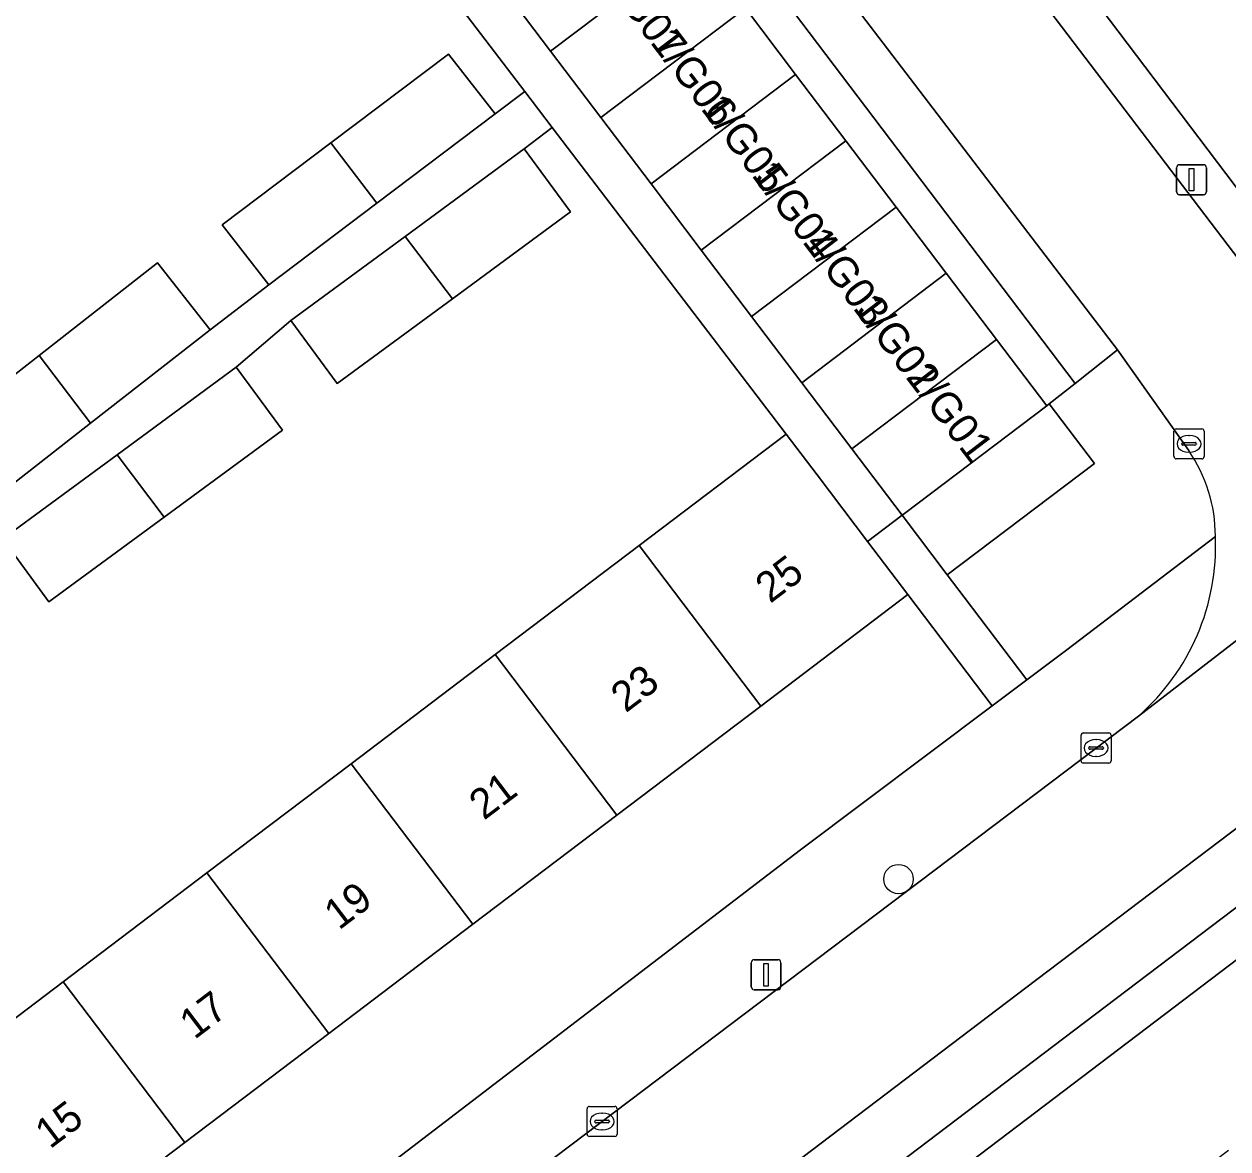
# Model space of a CAD drawing. Extents: x 160030 to 160839, y 385325 to 386450.
# Drawn here: x 160257.86 to 160297.9, y 385897.84 to 385935.27 of the extents above; entities that cross this region are included whole.
import ezdxf

# ---------------------------------------------------------------- set-up
doc = ezdxf.new("R2010")
doc.units = 0
for name, color, linetype in [('IMGEO_Boom', 7, 'Continuous'), ('IMGEO_Erf', 7, 'Continuous'), ('IMGEO_Groenvoorziening', 7, 'Continuous'), ('IMGEO_Kolk', 7, 'Continuous'), ('IMGEO_Lage_trafo', 7, 'Continuous'), ('IMGEO_Lichtmast', 7, 'Continuous'), ('IMGEO_Pand', 7, 'Continuous'), ('IMGEO_Pand_nummerreeks', 7, 'Continuous'), ('IMGEO_Parkeervlak_open', 7, 'Continuous'), ('IMGEO_Rijbaan_lokaal_open', 7, 'Continuous'), ('IMGEO_Voetpad_open', 7, 'Continuous')]:
    doc.layers.add(name, color=color, linetype=linetype)

msp = doc.modelspace()

# ---------------------------------------------------------------- linework, layer by layer
at = {"layer": 'IMGEO_Boom'}
msp.add_circle((160286.944, 385906.816), 0.489, dxfattribs=at)
at = {"layer": 'IMGEO_Erf'}
msp.add_lwpolyline([(160271.131, 385951.947), (160270.16, 385951.238), (160271.83, 385949.032), (160273.5, 385946.826), (160275.171, 385944.62), (160276.841, 385942.414), (160278.511, 385940.208), (160280.181, 385938.002), (160281.852, 385935.796), (160283.522, 385933.59), (160285.192, 385931.384), (160286.862, 385929.178), (160288.533, 385926.972), (160290.203, 385924.766), (160291.873, 385922.56), (160291.96, 385922.629), (160292.815, 385923.307)], close=True, dxfattribs=at)
for points in [[(160254.778, 385921.445), (160258.359, 385924.242), (160262.305, 385927.325), (160264.052, 385925.088), (160266.008, 385926.593), (160264.451, 385928.585), (160268.069, 385931.317), (160271.974, 385934.265), (160273.53, 385932.273), (160274.513, 385933.022), (160267.063, 385942.785)], [(160254.367, 385899.764), (160259.157, 385903.393), (160263.946, 385907.024), (160268.736, 385910.654), (160273.526, 385914.284), (160278.316, 385917.915), (160283.21, 385921.624), (160275.43, 385931.82), (160274.5, 385931.111), (160276.039, 385929.017), (160272.107, 385926.125), (160268.271, 385923.304), (160266.731, 385925.397), (160264.92, 385923.85), (160266.459, 385921.756), (160262.526, 385918.863), (160258.691, 385916.043), (160257.151, 385918.136)], [(160326.435, 385925.58), (160256.578, 385872.537), (160259.529, 385868.732), (160264.444, 385872.453), (160269.226, 385876.074), (160274.008, 385879.694), (160278.789, 385883.315), (160283.571, 385886.936), (160288.353, 385890.556), (160293.136, 385894.177), (160297.918, 385897.798)], [(160243.764, 385877.424), (160267.87, 385895.673), (160283.686, 385907.791), (160290.062, 385912.583), (160287.26, 385916.28), (160282.366, 385912.571), (160277.576, 385908.94), (160272.787, 385905.31), (160267.997, 385901.68), (160263.207, 385898.05), (160258.418, 385894.42), (160253.628, 385890.789)]]:
    msp.add_lwpolyline(points, dxfattribs=at)
at = {"layer": 'IMGEO_Groenvoorziening'}
msp.add_lwpolyline([(160296.595, 385921.073), (160294.227, 385924.426), (160292.815, 385923.307), (160291.96, 385922.629), (160293.467, 385920.64), (160288.567, 385916.938), (160289.125, 385916.201), (160291.211, 385913.446), (160292.54, 385914.445), (160297.485, 385918.22)], dxfattribs=at)
msp.add_arc((160292.466, 385918.22), 5.019, 0.0052, 34.6456, dxfattribs=at)
at = {"layer": 'IMGEO_Kolk'}
for p, q in [((160296.107, 385920.871), (160296.107, 385921.723)), ((160296.182, 385921.797), (160297.034, 385921.797)), ((160297.108, 385921.723), (160297.108, 385920.871)), ((160296.366, 385921.291), (160296.366, 385921.303)), ((160296.804, 385921.254), (160296.406, 385921.254)), ((160296.409, 385921.34), (160296.807, 385921.34)), ((160296.595, 385921.577), (160296.62, 385921.577)), ((160296.85, 385921.303), (160296.85, 385921.291)), ((160296.618, 385921.017), (160296.593, 385921.017)), ((160297.034, 385920.797), (160296.182, 385920.797)), ((160293.015, 385910.751), (160293.015, 385911.603)), ((160293.09, 385911.677), (160293.942, 385911.677)), ((160294.016, 385911.603), (160294.016, 385910.751)), ((160293.317, 385911.22), (160293.715, 385911.22)), ((160293.503, 385911.457), (160293.528, 385911.457)), ((160293.274, 385911.171), (160293.274, 385911.183)), ((160293.712, 385911.134), (160293.314, 385911.134)), ((160293.526, 385910.897), (160293.501, 385910.897)), ((160293.758, 385911.183), (160293.758, 385911.171)), ((160293.942, 385910.677), (160293.09, 385910.677)), ((160276.662, 385899.25), (160277.514, 385899.25)), ((160276.587, 385898.324), (160276.587, 385899.176)), ((160276.889, 385898.793), (160277.287, 385898.793)), ((160277.075, 385899.03), (160277.1, 385899.03)), ((160277.588, 385899.176), (160277.588, 385898.324)), ((160276.846, 385898.744), (160276.846, 385898.756)), ((160277.284, 385898.707), (160276.886, 385898.707)), ((160277.098, 385898.47), (160277.073, 385898.47)), ((160277.33, 385898.756), (160277.33, 385898.744)), ((160277.514, 385898.25), (160276.662, 385898.25))]:
    msp.add_line(p, q, dxfattribs=at)
for points in [[(160296.107, 385920.871), (160296.107, 385921.723)], [(160296.182, 385921.797), (160297.034, 385921.797)], [(160297.108, 385921.723), (160297.108, 385920.871)], [(160297.034, 385920.797), (160296.182, 385920.797)], [(160293.015, 385910.751), (160293.015, 385911.603)], [(160293.09, 385911.677), (160293.942, 385911.677)], [(160294.016, 385911.603), (160294.016, 385910.751)], [(160293.942, 385910.677), (160293.09, 385910.677)], [(160276.662, 385899.25), (160277.514, 385899.25)], [(160276.587, 385898.324), (160276.587, 385899.176)], [(160277.588, 385899.176), (160277.588, 385898.324)], [(160277.514, 385898.25), (160276.662, 385898.25)]]:
    msp.add_lwpolyline(points, dxfattribs=at)
for centre, radius, start, end in [((160296.184, 385921.721), 0.0765, 91.552, 178.448), ((160296.184, 385921.721), 0.0765, 91.552, 178.448), ((160297.032, 385921.721), 0.0765, 1.552, 88.448), ((160297.032, 385921.721), 0.0765, 1.552, 88.448), ((160296.406, 385921.3), 0.0403, 85.8775, 175.7526), ((160296.403, 385921.29), 0.0366, 178.938, 274.7102), ((160296.807, 385921.297), 0.043, 264.8664, 352.4533), ((160296.811, 385921.302), 0.0386, 1.7309, 96.639), ((160296.184, 385920.873), 0.0765, 181.552, 268.448), ((160296.184, 385920.873), 0.0765, 181.552, 268.448), ((160297.032, 385920.873), 0.0765, 271.552, 358.448), ((160297.032, 385920.873), 0.0765, 271.552, 358.448), ((160293.092, 385911.601), 0.0765, 91.552, 178.448), ((160293.092, 385911.601), 0.0765, 91.552, 178.448), ((160293.94, 385911.601), 0.0765, 1.552, 88.448), ((160293.94, 385911.601), 0.0765, 1.552, 88.448), ((160293.314, 385911.18), 0.0403, 85.8775, 175.7526), ((160293.719, 385911.182), 0.0386, 1.7309, 96.639), ((160293.311, 385911.17), 0.0366, 178.938, 274.7102), ((160293.715, 385911.177), 0.043, 264.8664, 352.4533), ((160293.092, 385910.753), 0.0765, 181.552, 268.448), ((160293.092, 385910.753), 0.0765, 181.552, 268.448), ((160293.94, 385910.753), 0.0765, 271.552, 358.448), ((160293.94, 385910.753), 0.0765, 271.552, 358.448), ((160276.664, 385899.174), 0.0765, 91.552, 178.448), ((160276.664, 385899.174), 0.0765, 91.552, 178.448), ((160277.512, 385899.174), 0.0765, 1.552, 88.448), ((160277.512, 385899.174), 0.0765, 1.552, 88.448), ((160276.886, 385898.753), 0.0403, 85.8775, 175.7526), ((160277.291, 385898.755), 0.0386, 1.7309, 96.639), ((160276.883, 385898.743), 0.0366, 178.938, 274.7102), ((160277.287, 385898.75), 0.043, 264.8664, 352.4533), ((160276.664, 385898.326), 0.0765, 181.552, 268.448), ((160276.664, 385898.326), 0.0765, 181.552, 268.448), ((160277.512, 385898.326), 0.0765, 271.552, 358.448), ((160277.512, 385898.326), 0.0765, 271.552, 358.448)]:
    msp.add_arc(centre, radius, start, end, dxfattribs=at)
for centre, major_axis, ratio, start_param, end_param in [((160296.594, 385921.297), (-0.387, 0.002), 0.722429, 4.712389, 7.853982), ((160296.619, 385921.297), (-0.39, 0.002), 0.717154, 1.570796, 4.712389), ((160293.502, 385911.177), (-0.387, 0.002), 0.722429, 4.712389, 7.853982), ((160293.527, 385911.177), (-0.39, 0.002), 0.717154, 1.570796, 4.712389), ((160277.074, 385898.75), (-0.387, 0.002), 0.722429, 4.712389, 7.853982), ((160277.099, 385898.75), (-0.39, 0.002), 0.717154, 1.570796, 4.712389)]:
    msp.add_ellipse(centre, major_axis=major_axis, ratio=ratio, start_param=start_param, end_param=end_param, dxfattribs=at)
at = {"layer": 'IMGEO_Lage_trafo'}
msp.add_lwpolyline([(160293.467, 385920.64), (160291.96, 385922.629), (160291.873, 385922.56), (160287.149, 385918.984), (160287.066, 385918.921), (160288.567, 385916.938)], close=True, dxfattribs=at)
at = {"layer": 'IMGEO_Lichtmast'}
for p, q in [((160296.194, 385929.686), (160296.194, 385930.486)), ((160296.194, 385930.486), (160296.194, 385929.686)), ((160296.294, 385930.586), (160297.084, 385930.586)), ((160297.084, 385930.586), (160296.294, 385930.586)), ((160297.184, 385930.486), (160297.184, 385929.686)), ((160297.184, 385929.686), (160297.184, 385930.486)), ((160297.084, 385929.586), (160296.294, 385929.586)), ((160296.294, 385929.586), (160297.084, 385929.586)), ((160282.043, 385903.232), (160282.043, 385904.032)), ((160282.043, 385904.032), (160282.043, 385903.232)), ((160282.143, 385904.132), (160282.933, 385904.132)), ((160282.933, 385904.132), (160282.143, 385904.132)), ((160283.033, 385904.032), (160283.033, 385903.232)), ((160283.033, 385903.232), (160283.033, 385904.032)), ((160282.933, 385903.132), (160282.143, 385903.132)), ((160282.143, 385903.132), (160282.933, 385903.132))]:
    msp.add_line(p, q, dxfattribs=at)
for points in [[(160296.614, 385930.461), (160296.764, 385930.461), (160296.764, 385929.711), (160296.614, 385929.711), (160296.614, 385930.461)], [(160282.463, 385904.007), (160282.613, 385904.007), (160282.613, 385903.257), (160282.463, 385903.257), (160282.463, 385904.007)]]:
    msp.add_lwpolyline(points, dxfattribs=at)
for centre, start, end in [((160296.294, 385930.486), 90, 180), ((160296.294, 385930.486), 90, 180), ((160297.084, 385930.486), 0, 90), ((160297.084, 385930.486), 360, 90), ((160296.294, 385929.686), 180, 270), ((160296.294, 385929.686), 180, 270), ((160297.084, 385929.686), 270, 0), ((160297.084, 385929.686), 270, 0), ((160282.143, 385904.032), 90, 180), ((160282.143, 385904.032), 90, 180), ((160282.933, 385904.032), 0, 90), ((160282.933, 385904.032), 360, 90), ((160282.143, 385903.232), 180, 270), ((160282.143, 385903.232), 180, 270), ((160282.933, 385903.232), 270, 0), ((160282.933, 385903.232), 270, 0)]:
    msp.add_arc(centre, 0.1, start, end, dxfattribs=at)
at = {"layer": 'IMGEO_Pand'}
msp.add_lwpolyline([(160274.238, 385961.479), (160300.528, 385926.728), (160311.028, 385934.695), (160315.959, 385938.476)], dxfattribs=at)
for points in [[(160280.181, 385938.002), (160278.511, 385940.208), (160273.704, 385936.569), (160275.375, 385934.363)], [(160275.375, 385934.363), (160277.045, 385932.157), (160281.852, 385935.796), (160280.181, 385938.002)], [(160277.045, 385932.157), (160278.715, 385929.951), (160283.522, 385933.59), (160281.852, 385935.796)], [(160273.53, 385932.273), (160271.974, 385934.265), (160268.069, 385931.317), (160269.596, 385929.302)], [(160285.192, 385931.384), (160283.522, 385933.59), (160278.715, 385929.951), (160280.385, 385927.745)], [(160269.596, 385929.302), (160268.069, 385931.317), (160264.451, 385928.585), (160266.008, 385926.593)], [(160280.385, 385927.745), (160282.056, 385925.539), (160286.862, 385929.178), (160285.192, 385931.384)], [(160272.107, 385926.125), (160276.039, 385929.017), (160274.5, 385931.111), (160270.537, 385928.196)], [(160288.533, 385926.972), (160286.862, 385929.178), (160282.056, 385925.539), (160283.726, 385923.333)], [(160270.537, 385928.196), (160266.731, 385925.397), (160268.271, 385923.304), (160272.107, 385926.125)], [(160260.073, 385921.98), (160264.052, 385925.088), (160262.305, 385927.325), (160258.359, 385924.242)], [(160290.203, 385924.766), (160288.533, 385926.972), (160283.726, 385923.333), (160285.396, 385921.127)], [(160291.873, 385922.56), (160290.203, 385924.766), (160285.396, 385921.127), (160287.066, 385918.921), (160287.149, 385918.984)], [(160258.359, 385924.242), (160254.778, 385921.445), (160256.525, 385919.209), (160260.073, 385921.98)], [(160262.526, 385918.863), (160266.459, 385921.756), (160264.92, 385923.85), (160260.956, 385920.934)], [(160284.24, 385920.265), (160283.21, 385921.624), (160278.316, 385917.915), (160282.366, 385912.571), (160287.26, 385916.28), (160285.917, 385918.052)], [(160260.956, 385920.934), (160257.151, 385918.136), (160258.691, 385916.043), (160262.526, 385918.863)], [(160282.366, 385912.571), (160278.316, 385917.915), (160273.526, 385914.284), (160277.576, 385908.94)], [(160277.576, 385908.94), (160273.526, 385914.284), (160268.736, 385910.654), (160272.787, 385905.31)], [(160272.787, 385905.31), (160268.736, 385910.654), (160263.946, 385907.024), (160267.997, 385901.68)], [(160267.997, 385901.68), (160263.946, 385907.024), (160259.157, 385903.393), (160263.207, 385898.05)], [(160263.207, 385898.05), (160259.157, 385903.393), (160254.367, 385899.764), (160258.418, 385894.42)]]:
    msp.add_lwpolyline(points, close=True, dxfattribs=at)
at = {"layer": 'IMGEO_Parkeervlak_open'}
for points in [[(160322.288, 385926.767), (160291.178, 385903.192), (160260.226, 385879.69), (160259.707, 385879.286)], [(160263.491, 385879.768), (160267.148, 385882.321), (160292.441, 385901.527), (160320.145, 385922.524)]]:
    msp.add_lwpolyline(points, dxfattribs=at)
at = {"layer": 'IMGEO_Rijbaan_lokaal_open'}
for points in [[(160274.289, 385958.969), (160272.271, 385961.56), (160271.801, 385962.176), (160269.121, 385965.683), (160266.287, 385963.609), (160265.109, 385962.726), (160268.311, 385958.528), (160272.504, 385952.949), (160278.21, 385945.409), (160294.227, 385924.426), (160296.595, 385921.073)], [(160300.632, 385924.328), (160300.493, 385924.507), (160299.426, 385925.902), (160274.289, 385958.969)], [(160322.288, 385926.767), (160324.349, 385928.333), (160321.054, 385932.279), (160320.872, 385932.139), (160309.303, 385923.348), (160309.139, 385923.215), (160294.924, 385912.241), (160272.144, 385895.008), (160250.573, 385878.611), (160236.592, 385867.964), (160232.453, 385864.762), (160226.524, 385860.463)], [(160229.444, 385856.309), (160248.486, 385870.73), (160253.767, 385874.761), (160259.317, 385878.983), (160259.707, 385879.286), (160260.226, 385879.69), (160291.178, 385903.192), (160322.288, 385926.767)], [(160294.924, 385912.241), (160309.139, 385923.215)]]:
    msp.add_lwpolyline(points, dxfattribs=at)
for centre, radius, start, end in [((160292.466, 385918.22), 5.019, 0.0052, 34.6456), ((160289.966, 385917.903), 7.526, 311.2089, 2.417)]:
    msp.add_arc(centre, radius, start, end, dxfattribs=at)
at = {"layer": 'IMGEO_Voetpad_open'}
for points in [[(160274.238, 385961.479), (160273.026, 385963.07), (160271.801, 385962.176), (160272.271, 385961.56), (160274.289, 385958.969), (160299.426, 385925.902), (160300.528, 385926.728)], [(160292.815, 385923.307), (160294.227, 385924.426), (160278.21, 385945.409), (160272.504, 385952.949), (160271.131, 385951.947)], [(160277.045, 385932.157), (160275.375, 385934.363), (160273.704, 385936.569), (160272.034, 385938.775), (160270.364, 385940.981), (160268.694, 385943.187), (160267.023, 385945.393), (160265.353, 385947.599), (160264.121, 385946.666), (160265.965, 385944.234), (160267.063, 385942.785), (160274.513, 385933.022), (160275.43, 385931.82), (160283.21, 385921.624), (160284.24, 385920.265), (160285.917, 385918.052), (160287.066, 385918.921), (160285.396, 385921.127), (160283.726, 385923.333), (160282.056, 385925.539), (160280.385, 385927.745), (160278.715, 385929.951)], [(160264.92, 385923.85), (160266.731, 385925.397), (160270.537, 385928.196), (160274.5, 385931.111), (160275.43, 385931.82), (160274.513, 385933.022), (160273.53, 385932.273), (160269.596, 385929.302), (160266.008, 385926.593), (160264.052, 385925.088), (160260.073, 385921.98), (160256.525, 385919.209), (160254.472, 385917.828), (160250.5, 385914.726), (160246.945, 385911.949), (160244.914, 385910.482), (160245.401, 385909.819), (160245.847, 385909.212), (160247.719, 385910.675), (160247.572, 385910.875), (160251.376, 385913.672), (160255.341, 385916.589), (160257.151, 385918.136), (160260.956, 385920.934)], [(160289.125, 385916.201), (160288.567, 385916.938), (160287.066, 385918.921), (160285.917, 385918.052), (160287.26, 385916.28), (160290.062, 385912.583), (160291.211, 385913.446)]]:
    msp.add_lwpolyline(points, close=True, dxfattribs=at)
for points in [[(160259.707, 385879.286), (160259.317, 385878.983), (160253.767, 385874.761), (160255.232, 385871.451), (160256.578, 385872.537), (160326.435, 385925.58)], [(160320.145, 385922.524), (160292.441, 385901.527), (160267.148, 385882.321), (160263.491, 385879.768)], [(160297.485, 385918.22), (160292.54, 385914.445), (160291.211, 385913.446), (160290.062, 385912.583), (160283.686, 385907.791), (160267.87, 385895.673), (160243.764, 385877.424), (160234.086, 385870.009), (160228.256, 385865.652), (160224.033, 385862.374)], [(160236.592, 385867.964), (160250.573, 385878.611), (160272.144, 385895.008), (160294.924, 385912.241)]]:
    msp.add_lwpolyline(points, dxfattribs=at)
msp.add_arc((160289.966, 385917.903), 7.526, 311.2089, 2.417, dxfattribs=at)

# ---------------------------------------------------------------- texts
at = {"layer": 'IMGEO_Pand_nummerreeks'}
for s, rotation, p in [('1/G07', 307.3301, (160276.972, 385936.871)), ('1/G06', 307.3301, (160278.659, 385934.66)), ('1/G05', 307.3301, (160280.346, 385932.448)), ('1/G04', 307.3301, (160282.033, 385930.236)), ('1/G03', 307.3301, (160283.719, 385928.024)), ('1/G02', 307.3301, (160285.402, 385925.817)), ('1/G01', 307.3301, (160287.16, 385923.513)), ('25', 37.1597, (160282.677, 385915.968)), ('23', 37.1597, (160277.872, 385912.326)), ('21', 37.1597, (160273.157, 385908.753)), ('19', 37.1597, (160268.334, 385905.097)), ('17', 37.1597, (160263.528, 385901.456)), ('15', 37.1597, (160258.723, 385897.814))]:
    msp.add_text(s, height=1, rotation=rotation, dxfattribs=at).set_placement(p)

doc.saveas('drawing.dxf')
